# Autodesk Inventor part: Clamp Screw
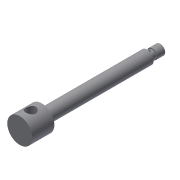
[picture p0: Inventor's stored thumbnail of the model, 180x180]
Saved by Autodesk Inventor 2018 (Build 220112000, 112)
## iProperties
Shininess: 77.0
Length Units: 11269
Angle Units: 11279
Time Units: 11290
Mass Units: 11283
Length Display Precision: 3
Angle Display Precision: 2
Created: 2002-02
Part Number: Clamp Screw
Document SubType Name: Modeling
Designer: ***
Density: 1 g/cm^3
Material: Generic
Mass: 23.4442 g
Surface Area: 81.4176 cm^2
Volume: 23.4442 cm^3
Appearance: Default
Density: 0.0
Volumn: 0.0
Area: 0.0
PropertySet Name: Model Information
Control State: 0
Master: False
Checked Out: False
Author: ***
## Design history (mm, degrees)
sketch "Sketch1"
  geometry: L1 (0, 140)-(5, 140); L2 (5, 140)-(5, 132); L3 (5, 132)-(4, 132); L4 (4, 132)-(4, 127); L5 (4, 127)-(6.5, 127); L6 (6.5, 127)-(6.5, 25); L7 (6.5, 25)-(4, 25); L8 (4, 25)-(4, 22); L9 (4, 22)-(12.5, 22); L10 (12.5, 22)-(12.5, 0); L11 (12.5, 0)-(0, 0); L12 (0, 0)-(0, 140)
  constraints: 24 end point, 10 parallel, 1 horizontal, 1 perpendicular
  dimensions: "d0" = 10 diameter of L2 L12; "d1" = 8 diameter of L4 L12; "d2" = 13 diameter of L6 L12; "d3" = 8 diameter of L7.end L12; "d4" = 25 diameter of L10 L12; "d5" = 3 distance from line of L7.end L9; "d6" = 8 distance of L1.end L2.end; "d7" = 13 vertical distance of L1.end L5.end; "d8" = 22 distance of L9.end L10.end; "d10" = 102 distance of L5.end L6.end
revolve "Revolution1" sketch "Sketch1" stored, may be unused: angle "d11" = 90 deg
sketch "Sketch3"
  geometry: L1 (-12.5, 0)-(12.5, 0) reference; C1 r 5 at (-0.113, 11)
  constraints: 1 centre point
  dimensions: "d13" = 10 diameter of C1; "d14" = 11 distance from line of L1 C1.centre
extrude "Extrusion1" cut sketch "Sketch3" extent not by distance; stored distance "d15" = 10; taper "d16" = 0 deg
sketch "Sketch4"
  geometry: L1 (0, 138.841)-(0, 0); L2 (-12.5, 0)-(12.5, 0) reference; L3 (-5, 140)-(5, 140) reference; C1 r 1 at (0, 129.5)
  constraints: 2 end point, 1 centre point, 1 point on line, 1 vertical
  dimensions: "d17" = 2 diameter of C1; "d18" = 10.5 distance from line of L3 C1.centre
extrude "Extrusion2" cut sketch "Sketch4" stored distance "d19" = 10; taper "d20" = 0 deg
body "Solid1"
